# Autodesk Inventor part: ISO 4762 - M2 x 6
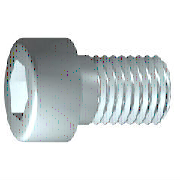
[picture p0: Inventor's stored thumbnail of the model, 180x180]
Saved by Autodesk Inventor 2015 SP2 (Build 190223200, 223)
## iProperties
Created: 2012-02
Part Number: ISO 4762 - M2 x 6
Material: Edelstahl, 440C
Description: Innensechskantschraube
Document SubType Name: Modeling
Standard: ISO 4762
Designer: rYan
Standard Revision: 1998
Standards Organization: DIN
Language: de-DE
Size Designation: M2 x 6
Categories: <MemberInstance><Categories><Category DisplayName="Verbindungselemente" InternalName="e4da775c-781d-43d5-af7c-5136215cf5a6" Mnemonic="FSTN"><Category DisplayNam
Density: 7.75 g/cm^3
Appearance: Halbpoliert
IsCustomPart: 0
Author: rYan
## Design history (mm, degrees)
sketch "Skizze1"
  geometry: L1 (-0.5, 0)-(6, 0); L2 (6, 0)-(6, 1); L3 (6, 1)-(1, 1); L4 (1, 1)-(0.755, 1); L5 (0.755, 1)-(0, 1); L6 (0, 1)-(0, 1.9); L7 (0, 1.9)-(-2, 1.9); L8 (-2, 1.9)-(-2, 0.866); L9 (-2, 0.866)-(-1, 0.866); L10 (-1, 0.866)-(-0.5, 0); L11 (-3.6, 0)-(7.6, 0) reference; L12 (0, -0.38)-(0, 2.28) reference; L13 (1, 1)-(0, 1)
  constraints: 22 end point, 6 parallel, 2 collinear, 2 perpendicular, 1 horizontal, 1 point on line
  dimensions: "d1" = 5 distance from line of L3.end L2 (= GEL); "d2" = 0.24548 distance of L4.end L3.end (computed from GAL); "d3" = 2 distance between parallel lines of L8 L6 (= KOH); "d4" = 1 distance of L8.end L9.end (= INTI); "d5" = 60 deg angle of L10 L1; "d6" = 2 diameter of L3 L1 (= GD); "d7" = 2 diameter of L5 L1 (= BDM); "d8" = 1.73205 diameter of L9 L1 (= 1.1547 x SW); "d9" = 3.8 diameter of L7 L1 (= KOD); "d26" = 6 distance between parallel lines of L12 L2 (= NLG)
revolve "Körper" sketch "Skizze1" stored, may be unused: angle "d10" = 90 deg
sketch "Skizze2"
  geometry: L1 (0, -2.66)-(0, 2.66) reference; L2 (-2.66, 0)-(2.66, 0) reference; L3 (0.866, 0)-(0.433, -0.75); L4 (0.433, -0.75)-(-0.433, -0.75); L5 (-0.433, -0.75)-(-0.866, 0); L6 (-0.866, 0)-(-0.433, 0.75); L7 (-0.433, 0.75)-(0.433, 0.75); L8 (0.433, 0.75)-(0.866, 0); 2 further points
  constraints: 12 end point, 1 coincident, 1 horizontal alignment, 1 point on line, 12 other
extrude "Loch" join sketch "Skizze2" stored distance "d11" = 10; taper "d12" = 0 deg
workplane "Work Plane1"
fillet "Fillet2" dims "d30" = 0.1 (= R)
body "Solid1"
fillet "Rundung1" dims "d17" = 0.2 (= RR)
feature "Gewinde" dims "d13" = 5 (= GEL), "d14" = 0
chamfer "Fase1" distance "d15" = 0.24538 (= -0.5 x SPD + 0.5 x GD); stored, may be unused: second distance "d16" = 0.24538 (= GUL), angle "d27" = 45 deg
other parameters: "GD" = 2 [user parameter; used in 2 equation terms], "NLG" = 6 [user parameter; used in 1 equation term], "GEL" = 5 [user parameter; used in 2 equation terms], "KOD" = 3.8 [user parameter; used in 1 equation term], "KOH" = 2 [user parameter; used in 1 equation term], "INTI" = 1 [user parameter; used in 1 equation term], "GAL" = 0.24538 (= 0.61345 x PTC) [user parameter; used in 1 equation term], "GUL" = 0.24538 (= 0.61345 x PTC) [user parameter; used in 1 equation term], "BDM" = 2 (= NND) [user parameter; used in 1 equation term], "SW" = 1.5 [user parameter; used in 2 equation terms], "RR" = 0.2 [user parameter; used in 1 equation term], "SPD" = 1.50924 (= NND - 1.2269 x PTC) [user parameter; used in 1 equation term], "d19" = 0, "d28" = 0, "d29" = 0, "R" = 0.1 [user parameter; used in 1 equation term], "TOA" = 30 deg [user parameter], "GD1" = 1.50924 (= THREADDIA - 1.2269 x PTC) [user parameter], "THREADDIA" = 2 [user parameter; used in 1 equation term], "FAWI" = 45 deg [user parameter], "TPU" = 25 (computed from PTC) [user parameter], "PTC" = 0.4 [user parameter; used in 5 equation terms], "NND" = 2 [user parameter; used in 2 equation terms], "E0" = 1.7325 (= 1.155 x SW) [user parameter]
